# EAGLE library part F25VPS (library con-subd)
SUB-D
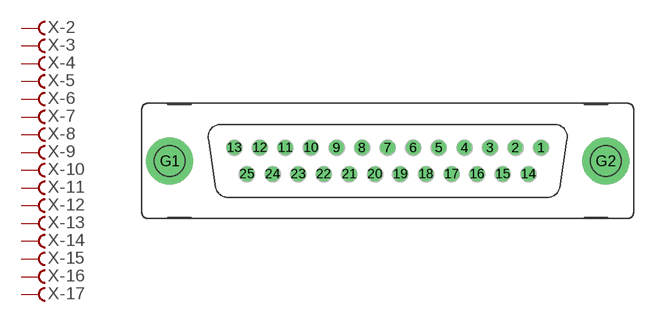
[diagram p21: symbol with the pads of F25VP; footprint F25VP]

Designator prefix X; gates -2=F -3=F -4=F -5=F -6=F -7=F -8=F -9=F -10=F -11=F -12=F -13=F -14=F -15=F -16=F -17=F -18=F -19=F -20=F -21=F -22=F -23=F -24=F -25=F -G=GND -1=FV

## F25VPS (OC_FARNELL: unknown; OC_NEWARK: unknown)  [F25VP]
1  -1:F  pas
2  -2:F  pas
3  -3:F  pas
4  -4:F  pas
5  -5:F  pas
6  -6:F  pas
7  -7:F  pas
8  -8:F  pas
9  -9:F  pas
10  -10:F  pas
11  -11:F  pas
12  -12:F  pas
13  -13:F  pas
14  -14:F  pas
15  -15:F  pas
16  -16:F  pas
17  -17:F  pas
18  -18:F  pas
19  -19:F  pas
20  -20:F  pas
21  -21:F  pas
22  -22:F  pas
23  -23:F  pas
24  -24:F  pas
25  -25:F  pas
G1  -G:G1  pas
G2  -G:G2  pas

## Footprint F25VP (pad centres in mm)
SUB-D
drill 1.016 octagon: 1 16.561,1.422; 2 13.792,1.422; 3 11.049,1.422; 4 8.28,1.422; 5 5.512,1.422; 6 2.769,1.422; 7 0,1.422; 8 -2.769,1.422; 9 -5.512,1.422; 10 -8.28,1.422; 11 -11.049,1.422; 12 -13.792,1.422; 13 -16.561,1.422; 14 15.189,-1.422; 15 12.421,-1.422; 16 9.652,-1.422; 17 6.909,-1.422; 18 4.14,-1.422; 19 1.372,-1.422; 20 -1.372,-1.422; 21 -4.14,-1.422; 22 -6.909,-1.422; 23 -9.652,-1.422; 24 -12.421,-1.422; 25 -15.189,-1.422
drill 3.302 pad 5.08 round: G1 -23.52,0; G2 23.52,0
